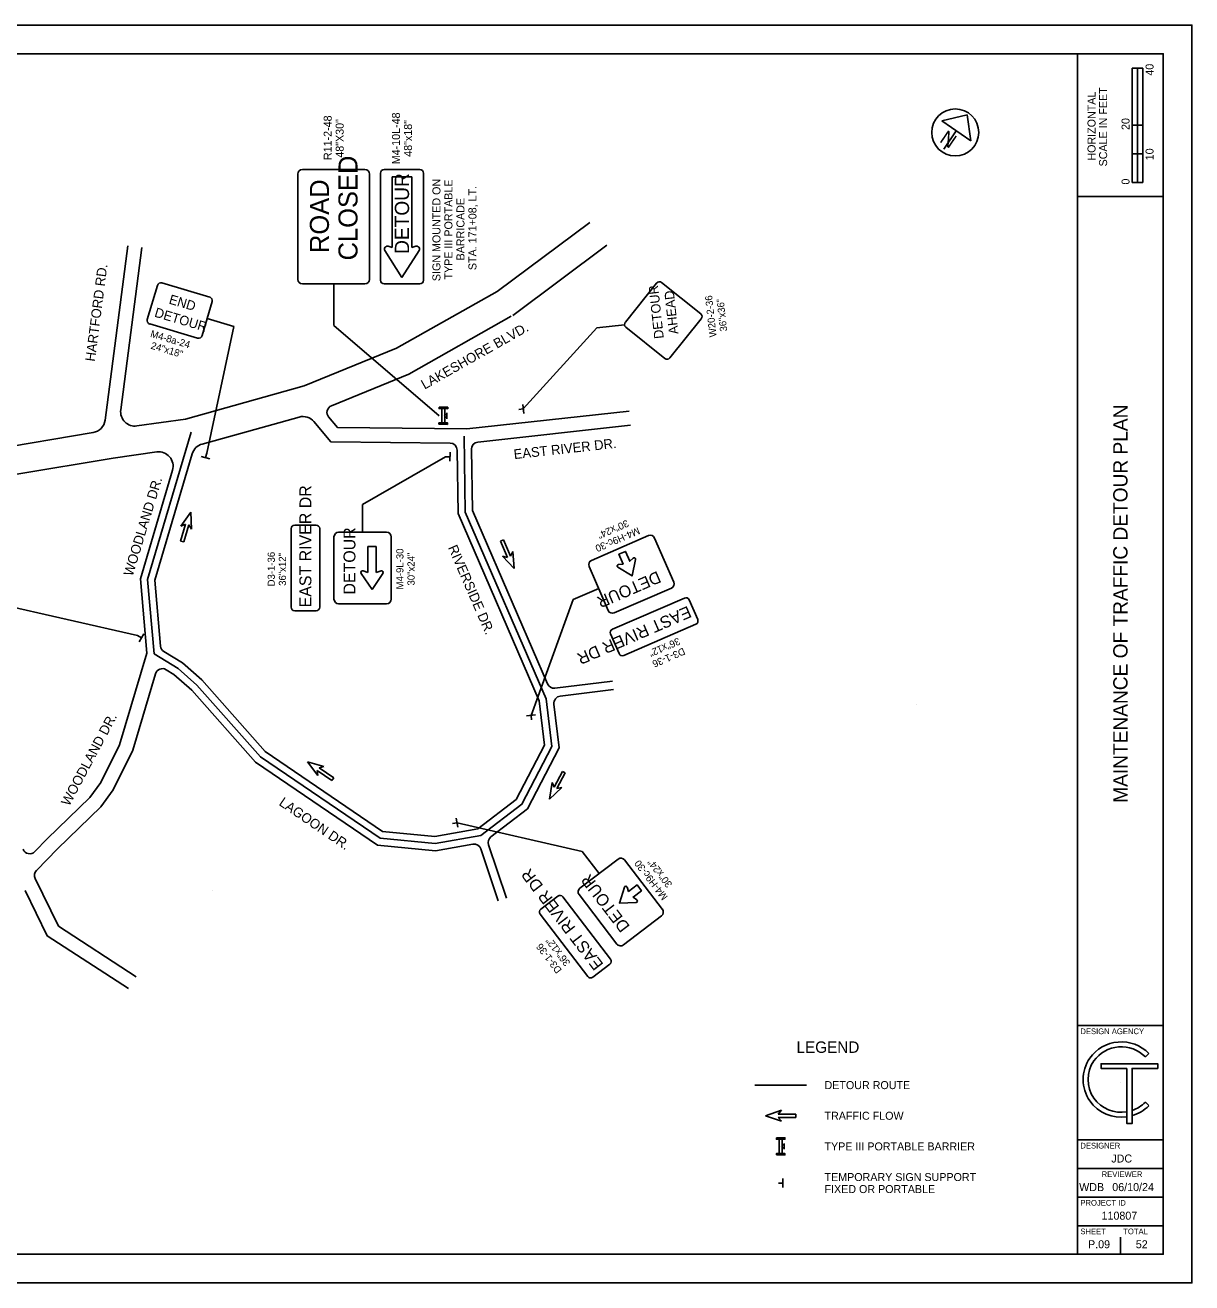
# Model space of a CAD drawing. Extents: x 0 to 680, y 0 to 440.
# Drawn here: x 271.8 to 680, y 0 to 440 of the extents above; entities that cross this region are included whole.
import ezdxf

# ---------------------------------------------------------------- set-up
doc = ezdxf.new("R2010")
doc.units = 0
for name, color, linetype in [('MT_P_Cells', 7, 'Continuous'), ('MT_P_Temp_Road', 7, 'Continuous'), ('PV_X_EOP', 7, 'Continuous'), ('SH_Border', 7, 'Continuous'), ('SH_Cut_Line', 7, 'Continuous'), ('SH_Data', 7, 'Continuous'), ('SH_Masking', 7, 'Continuous'), ('SH_Text', 7, 'Continuous'), ('SN_P_Signs', 7, 'Continuous'), ('SN_P_Text', 7, 'Continuous')]:
    doc.layers.add(name, color=color, linetype=linetype)

msp = doc.modelspace()

# ---------------------------------------------------------------- linework, layer by layer
at = {"layer": 'MT_P_Cells'}
for p, q in [((417.59, 300.84), (417.64, 305.84)), ((418.59, 300.83), (418.64, 305.83)), ((418.62, 303.83), (419.37, 303.82)), ((419.38, 304.32), (419.35, 302.32)), ((446.09, 305.73), (444.5, 305.56)), ((445.91, 307.32), (446.26, 304.14)), ((418.12, 303.34), (418.12, 303.34)), ((418.61, 302.83), (419.36, 302.82)), ((420.46, 290.61), (420.43, 287.41)), ((336.42, 288.24), (333.35, 289.15)), ((334.89, 288.7), (335.34, 290.23)), ((420.45, 289.01), (418.85, 289.02)), ((312.53, 225.63), (311.16, 226.47)), ((313.36, 227), (311.69, 224.27)), ((447.23, 198.34), (450.41, 198.73)), ((448.82, 198.54), (449.01, 196.95)), ((422.94, 160.95), (421.36, 160.67)), ((422.66, 162.52), (423.22, 159.37)), ((535.65, 45.24), (535.65, 50.24)), ((536.65, 45.24), (536.65, 50.24)), ((537.4, 48.74), (537.4, 46.74)), ((536.15, 47.74), (536.15, 47.74)), ((536.65, 48.24), (537.4, 48.24)), ((536.65, 47.24), (537.4, 47.24)), ((536.95, 36.51), (536.95, 33.31)), ((536.95, 34.91), (535.35, 34.91))]:
    msp.add_line(p, q, dxfattribs=at)
for points in [[(416.65, 306.35), (419.65, 306.32), (419.64, 305.82), (416.64, 305.85)], [(416.58, 300.35), (419.58, 300.32), (419.59, 300.82), (416.59, 300.85)], [(534.65, 50.74), (537.65, 50.74), (537.65, 50.24), (534.65, 50.24)], [(534.65, 44.74), (537.65, 44.74), (537.65, 45.24), (534.65, 45.24)]]:
    msp.add_lwpolyline(points, close=True, dxfattribs=at)
at = {"layer": 'MT_P_Temp_Road'}
msp.add_line((545.23, 69.18), (527.06, 69.18), dxfattribs=at)
for points in [[(329.91, 297.58), (314.66, 246.1), (316.9, 220.03)], [(316.9, 220.03), (325.35, 214.87), (331.87, 209.14), (354.12, 184), (396.01, 155.53), (415.23, 153.68), (431.28, 156.5), (445.59, 167.46), (456.13, 187.62), (454.1, 204.3), (425.78, 269.64), (425.4, 296.25)]]:
    msp.add_lwpolyline(points, dxfattribs=at)
at = {"layer": 'PV_X_EOP'}
for p, q in [((469.34, 371), (436.93, 346.85)), ((299.76, 301.75), (307.7, 362.83)), ((305.27, 305.38), (312.66, 362.18)), ((475.31, 362.98), (442.4, 338.46)), ((367.66, 302.88), (333.74, 293.46)), ((483.64, 300), (430.2, 294.13)), ((457.14, 208.06), (477.31, 210.51)), ((459.02, 205.27), (477.68, 207.53)), ((431.28, 151.8), (437.36, 133.65)), ((433.95, 153.27), (440.2, 134.6))]:
    msp.add_line(p, q, dxfattribs=at)
for points in [[(436.93, 346.85), (401.74, 326.97), (369.47, 313.77), (327.91, 302.21), (310.94, 299.79)], [(441.85, 338.15), (406.11, 317.95), (378.95, 306.84)], [(483.1, 304.97), (426.37, 298.74), (381.08, 299.25), (377.99, 302.92)], [(420.5, 293.81), (378.74, 294.27), (372.82, 301.29)], [(295.62, 297.47), (259.75, 291.47), (178.55, 287.16)], [(317.87, 290.68), (302.57, 288.49), (268.91, 282.86)], [(422.97, 291.34), (423.29, 269.1), (451.66, 203.64), (453.55, 188.09), (443.63, 169.11), (430.25, 158.86), (415.14, 156.2), (396.89, 157.96), (355.78, 185.9), (333.64, 210.91), (326.83, 216.89), (320.36, 220.85)], [(427.97, 291.61), (428.27, 270.18), (454.55, 209.55)], [(319.18, 222.77), (317.2, 245.84), (330.29, 290.06)], [(275.2, 150.86), (279.56, 155.36), (294.5, 169.77), (298.31, 175.03), (304.8, 188.23), (314.37, 220.29), (312.13, 246.35), (323.37, 284.31)], [(275.79, 144.3), (283.09, 151.82), (298.29, 166.48), (302.61, 172.45), (309.47, 186.4), (317.44, 213.1)], [(428.47, 153.47), (415.33, 151.16), (395.13, 153.11), (352.45, 182.11), (330.1, 207.36), (323.86, 212.85), (321.14, 214.51)], [(456.84, 202.48), (458.7, 187.15), (447.55, 165.82), (434.8, 156.05)], [(310.65, 107.11), (283.45, 124.83), (275.34, 141.46)], [(307.93, 102.92), (279.57, 121.39), (271.82, 137.28)]]:
    msp.add_lwpolyline(points, dxfattribs=at)
for centre, radius, start, end in [((310.23, 304.74), 5, 172.5857, 278.1351), ((379.9, 304.53), 2.5, 112.2489, 220.1465), ((294.8, 302.4), 5, 279.4984, 352.5857), ((369, 298.07), 5, 40.1465, 105.5343), ((318.57, 285.73), 5, 343.5091, 98.1351), ((335.08, 288.64), 5, 105.5343, 163.5091), ((420.47, 291.31), 2.5, 0.8092, 89.3564), ((430.47, 291.64), 2.5, 96.2649, 180.8092), ((321.67, 222.98), 2.5, 184.9071, 238.5787), ((319.84, 212.38), 2.5, 58.5787, 163.3828), ((456.84, 210.54), 2.5, 203.4328, 276.9327), ((459.32, 202.78), 2.5, 96.9327, 186.9327), ((436.32, 154.06), 2.5, 127.4637, 198.522), ((273.4, 152.6), 2.5, 201.1573, 315.8904), ((428.91, 151.01), 2.5, 18.522, 99.9801), ((277.59, 142.56), 2.5, 135.8904, 206.0049)]:
    msp.add_arc(centre, radius, start, end, dxfattribs=at)
at = {"layer": 'SH_Border'}
for p, q in [((640, 10), (640, 430)), ((640, 380), (670, 380)), ((640, 90), (670, 90)), ((640, 50), (670, 50)), ((640, 40), (670, 40)), ((640, 30), (670, 30)), ((640, 20), (670, 20))]:
    msp.add_line(p, q, dxfattribs=at)
msp.add_lwpolyline([(30, 430), (670, 430), (670, 10), (30, 10)], close=True, dxfattribs=at)
at = {"layer": 'SH_Cut_Line'}
msp.add_lwpolyline([(0, 0), (680, 0), (680, 440), (0, 440)], close=True, dxfattribs=at)
at = {"layer": 'SH_Data'}
for p, q in [((659.13, 385), (659.13, 425)), ((662.88, 425), (659.13, 425)), ((659.13, 405), (659.13, 425)), ((659.13, 425), (661, 425)), ((661, 425), (661.02, 425)), ((661.02, 425), (661.02, 405)), ((662.88, 425), (662.88, 385)), ((661.02, 405), (659.13, 405)), ((662.87, 405), (661, 405)), ((661, 405), (661, 395)), ((662.87, 395), (662.87, 405)), ((661, 395), (659.13, 395)), ((659.13, 395), (659.13, 385)), ((661, 395), (662.87, 395)), ((661, 385), (661, 395)), ((662.88, 385), (659.13, 385)), ((659.13, 385), (661, 385)), ((655, 70), (655, 70)), ((647.5, 13.5), (647.5, 13.5)), ((655, 10), (655, 16))]:
    msp.add_line(p, q, dxfattribs=at)
at = {"layer": 'SH_Masking'}
msp.add_circle((597.22, 402.47), 8.2, dxfattribs=at)
at = {"layer": 'SH_Text'}
for p, q in [((601.44, 408.64), (592.51, 406.48)), ((592.51, 406.48), (602.66, 399.54)), ((602.66, 399.54), (601.44, 408.64)), ((597.59, 403.01), (593.22, 396.62)), ((379.76, 349.48), (379.76, 334.9)), ((335.34, 290.23), (344.81, 334.57)), ((344.81, 334.57), (335.49, 337.33)), ((416.62, 303.35), (379.76, 334.9)), ((481.53, 335.18), (471.87, 334.12)), ((446.09, 305.73), (471.87, 334.12)), ((418.85, 289.02), (389.87, 272.3)), ((329.78, 269.62), (326.31, 264.78)), ((329.78, 269.62), (329.78, 269.62)), ((330.05, 263.67), (329.78, 269.62)), ((389.87, 262.58), (389.87, 272.3)), ((327.96, 265.47), (326.2, 259.53)), ((326.31, 264.78), (327.96, 265.47)), ((327.28, 259.21), (329.04, 265.15)), ((329.04, 265.15), (330.05, 263.67)), ((438.09, 259.47), (439.12, 259.91)), ((438.61, 259.69), (438.61, 259.69)), ((439.12, 259.91), (441.58, 254.24)), ((326.2, 259.53), (327.28, 259.21)), ((326.74, 259.37), (326.74, 259.37)), ((440.55, 253.79), (438.09, 259.47)), ((441.58, 254.24), (442.41, 255.82)), ((442.41, 255.82), (442.86, 249.88)), ((442.86, 249.88), (438.83, 254.27)), ((438.83, 254.27), (440.55, 253.79)), ((442.86, 249.88), (442.86, 249.88)), ((311.16, 226.47), (238, 243.02)), ((472.47, 242.92), (463.55, 239.06)), ((448.82, 198.54), (463.55, 239.06)), ((370.62, 182.24), (370.62, 182.24)), ((370.62, 182.24), (376.37, 180.69)), ((374.17, 177.46), (370.62, 182.24)), ((376.37, 180.69), (374.65, 180.17)), ((379.14, 175.76), (374.02, 179.24)), ((374.02, 179.24), (374.17, 177.46)), ((374.65, 180.17), (379.77, 176.7)), ((379.77, 176.7), (379.14, 175.76)), ((379.45, 176.23), (379.45, 176.23)), ((456.89, 173.44), (459.76, 178.92)), ((460.75, 178.4), (457.89, 172.91)), ((459.76, 178.92), (460.75, 178.4)), ((460.26, 178.66), (460.26, 178.66)), ((455.3, 169.19), (456.18, 175.08)), ((459.64, 173.27), (455.3, 169.19)), ((456.18, 175.08), (456.89, 173.44)), ((457.89, 172.91), (459.64, 173.27)), ((455.3, 169.19), (455.3, 169.19)), ((422.94, 160.95), (466.67, 150.88)), ((472.59, 143.16), (466.67, 150.88)), ((664.98, 80.27), (663.74, 79.05)), ((664.98, 80.27), (663.74, 79.05)), ((668.05, 76.67), (648.27, 76.67)), ((648.27, 76.67), (648.27, 75.02)), ((648.27, 75.02), (657.27, 75.02)), ((657.27, 75.02), (657.27, 55.7)), ((659.11, 55.7), (659.11, 75.02)), ((659.11, 75.02), (668.05, 75.02)), ((668.05, 75.02), (668.05, 76.67)), ((663.74, 63.21), (664.98, 61.99)), ((663.74, 63.21), (664.98, 61.99)), ((530.8, 58.46), (536.43, 60.41)), ((530.8, 58.46), (536.43, 60.41)), ((530.8, 58.46), (530.8, 58.46)), ((536.43, 56.51), (530.8, 58.46)), ((530.8, 58.46), (530.8, 58.46)), ((536.43, 56.51), (530.8, 58.46)), ((536.43, 60.41), (535.3, 59.02)), ((536.43, 60.41), (535.3, 59.02)), ((535.3, 59.02), (541.49, 59.02)), ((535.3, 59.02), (541.49, 59.02)), ((541.49, 57.9), (535.3, 57.9)), ((535.3, 57.9), (536.43, 56.51)), ((541.49, 57.9), (535.3, 57.9)), ((535.3, 57.9), (536.43, 56.51)), ((541.49, 59.02), (541.49, 57.9)), ((541.49, 59.02), (541.49, 57.9)), ((541.49, 58.46), (541.49, 58.46)), ((541.49, 58.46), (541.49, 58.46)), ((657.27, 59.86), (657.27, 58.09)), ((657.27, 59.86), (657.27, 58.09)), ((659.11, 58.5), (659.11, 60.32)), ((659.11, 58.5), (659.11, 60.32)), ((657.27, 55.7), (659.11, 55.7))]:
    msp.add_line(p, q, dxfattribs=at)
msp.add_lwpolyline([(657.27, 75.02), (657.27, 55.7), (659.11, 55.7), (659.11, 75.02), (668.05, 75.02), (668.05, 76.67), (648.27, 76.67), (648.27, 75.02)], close=True, dxfattribs=at)
msp.add_circle((597.22, 402.47), 8.2, dxfattribs=at)
for centre, radius, start, end in [((655.31, 70.7), 13.6, 44.7027, 144.3276), ((655.31, 70.7), 13.6, 44.7027, 144.3276), ((655.31, 70.7), 11.86, 44.7362, 144.1102), ((655.31, 70.7), 11.86, 44.7362, 144.1102), ((655.28, 71.13), 13.33, 145.7329, 214.2671), ((655.28, 71.13), 13.33, 145.7329, 214.2671), ((655.28, 71.13), 11.59, 145.7266, 214.2734), ((655.28, 71.13), 11.59, 145.7266, 214.2734), ((655.31, 71.55), 13.6, 215.6724, 278.2613), ((655.31, 71.55), 13.6, 215.6724, 278.2613), ((655.31, 71.55), 11.86, 215.8898, 279.4882), ((655.31, 71.55), 11.86, 215.8898, 279.4882), ((655.31, 71.55), 11.86, 288.6992, 315.2638), ((655.31, 71.55), 11.86, 288.6992, 315.2638), ((655.31, 71.55), 13.6, 286.2291, 315.2973), ((655.31, 71.55), 13.6, 286.2291, 315.2973)]:
    msp.add_arc(centre, radius, start, end, dxfattribs=at)
at = {"layer": 'SN_P_Signs'}
for p, q in [((400.22, 362.19), (400.22, 386.98)), ((400.22, 386.98), (407.09, 386.98)), ((407.09, 386.98), (407.09, 362.19)), ((403.66, 351.77), (397.68, 361.14)), ((398.83, 362.63), (400.22, 362.19)), ((409.63, 361.14), (403.66, 351.77)), ((407.09, 362.19), (408.48, 362.63)), ((391.74, 248.52), (391.74, 257.58)), ((391.74, 257.58), (394.66, 257.58)), ((394.66, 257.58), (394.66, 248.52)), ((393.2, 242.58), (389.39, 248.2)), ((390.04, 249.06), (391.74, 248.52)), ((397.01, 248.2), (393.2, 242.58)), ((394.66, 248.52), (396.36, 249.06)), ((583.6, 202.3), (583.6, 202.29)), ((337.52, 137.1), (337.52, 137.09))]:
    msp.add_line(p, q, dxfattribs=at)
for points in [[(367.26, 351.04), (367.26, 387.91)], [(368.82, 389.48), (390.69, 389.48)], [(392.26, 387.91), (392.26, 351.04)], [(396.16, 388.23), (396.16, 350.73)], [(409.91, 389.48), (397.41, 389.48)], [(411.16, 350.73), (411.16, 388.23)], [(318.08, 348.95), (314.56, 337.06)], [(336.38, 344.89), (319.69, 349.83)], [(390.69, 349.48), (368.82, 349.48)], [(397.41, 349.48), (409.91, 349.48)], [(481.8, 336.1), (492.75, 349.75)], [(494.51, 349.95), (508.16, 339)], [(333.73, 331.39), (337.25, 343.28)], [(315.43, 335.45), (332.12, 330.51)], [(508.35, 337.24), (497.4, 323.59)], [(495.64, 323.4), (481.99, 334.35)], [(379.87, 239.18), (379.87, 260.98)], [(381.47, 262.58), (398.27, 262.58)], [(399.87, 260.98), (399.87, 239.18)], [(398.27, 237.58), (381.47, 237.58)]]:
    msp.add_lwpolyline(points, dxfattribs=at)
for centre, radius, start, end in [((368.82, 387.91), 1.57, 90, 180), ((390.69, 387.91), 1.57, 0, 90), ((397.41, 388.23), 1.25, 90, 180), ((409.91, 388.23), 1.25, 0, 90), ((398.52, 361.68), 1, 72.1811, 212.5109), ((408.79, 361.68), 1, 327.4891, 107.8189), ((319.32, 348.58), 1.3, 73.5091, 163.5091), ((368.82, 351.04), 1.57, 180, 270), ((390.69, 351.04), 1.57, 270, 0), ((397.41, 350.73), 1.25, 180, 270), ((409.91, 350.73), 1.25, 270, 0), ((493.72, 348.97), 1.25, 51.2649, 141.2649), ((336.01, 343.65), 1.3, 343.5091, 73.5091), ((507.38, 338.02), 1.25, 321.2649, 51.2649), ((315.8, 336.69), 1.3, 163.5091, 253.5091), ((482.77, 335.32), 1.25, 141.2649, 231.2649), ((332.49, 331.76), 1.3, 253.5091, 343.5091), ((496.43, 324.37), 1.25, 231.2649, 321.2649), ((381.47, 260.98), 1.6, 90, 180), ((398.27, 260.98), 1.6, 360, 90), ((389.87, 248.52), 0.572, 72.1992, 214.1969), ((396.53, 248.52), 0.572, 325.8031, 107.8008), ((381.47, 239.18), 1.6, 180, 270), ((398.27, 239.18), 1.6, 270, 360)]:
    msp.add_arc(centre, radius, start, end, dxfattribs=at)
at = {"layer": 'SN_P_Text'}
for p, q in [((481.85, 255.87), (479.53, 254.87)), ((483.32, 252.49), (481.85, 255.87)), ((481.01, 251.47), (479.4, 251.3)), ((483.33, 252.47), (483.32, 252.49)), ((484.55, 253.53), (483.33, 252.47)), ((484.17, 247.34), (485.35, 253.06)), ((479.19, 250.39), (484.17, 247.34)), ((481.46, 138.45), (479.71, 132.88)), ((482.95, 136.95), (482.4, 138.47)), ((484.5, 134.95), (487.43, 137.19)), ((487.43, 137.19), (485.89, 139.2)), ((479.71, 132.88), (485.55, 133.12)), ((484.49, 134.94), (484.5, 134.95)), ((485.81, 134.02), (484.49, 134.94))]:
    msp.add_line(p, q, dxfattribs=at)
for points in [[(366.12, 265.11), (373.62, 265.11)], [(364.87, 263.86), (364.87, 236.36)], [(374.87, 236.36), (374.87, 263.86)], [(489.96, 261.4), (469.96, 252.73)], [(498.74, 245.16), (492.06, 260.57)], [(479.4, 251.3), (481.01, 251.47), (479.53, 254.87), (481.85, 255.87), (483.33, 252.47), (484.55, 253.53)], [(485.35, 253.06), (484.17, 247.34), (479.19, 250.39)], [(479.53, 254.87), (481, 251.48)], [(469.12, 250.63), (475.81, 235.22)], [(477.91, 234.38), (497.91, 243.05)], [(502.49, 239.59), (477.26, 228.65)], [(507.11, 232.06), (504.13, 238.94)], [(366.12, 235.11), (373.62, 235.11)], [(481.23, 219.48), (506.46, 230.41)], [(479.59, 220.13), (476.61, 227.01)], [(479.25, 148.27), (465.92, 138.05)], [(494.76, 130.67), (481.5, 147.98)], [(485.55, 133.12), (479.71, 132.88), (481.46, 138.45)], [(482.4, 138.47), (482.95, 136.95), (485.89, 139.2), (487.43, 137.19), (484.49, 134.94), (485.81, 134.02)], [(485.89, 139.2), (482.96, 136.96)], [(452.2, 130.73), (458.15, 135.29)], [(476.63, 113.23), (459.9, 135.06)], [(465.62, 135.81), (478.88, 118.51)], [(451.96, 128.97), (468.69, 107.15)], [(481.13, 118.21), (494.46, 128.43)], [(470.44, 106.91), (476.4, 111.48)]]:
    msp.add_lwpolyline(points, dxfattribs=at)
for centre, radius, start, end in [((366.12, 263.86), 1.25, 90, 180), ((373.62, 263.86), 1.25, 0, 90), ((490.59, 259.94), 1.6, 23.4328, 113.4328), ((470.59, 251.27), 1.6, 113.4328, 203.4328), ((479.45, 250.81), 0.493, 95.795, 238.5121), ((479.45, 250.81), 0.493, 95.795, 238.5121), ((484.87, 253.16), 0.493, 348.3536, 131.0707), ((484.87, 253.16), 0.493, 348.3536, 131.0707), ((497.28, 244.52), 1.6, 293.4328, 23.4328), ((502.99, 238.44), 1.25, 23.4328, 113.4328), ((366.12, 236.36), 1.25, 180, 270), ((373.62, 236.36), 1.25, 270, 0), ((477.27, 235.85), 1.6, 203.4328, 293.4328), ((505.97, 231.56), 1.25, 293.4328, 23.4328), ((477.75, 227.5), 1.25, 113.4328, 203.4328), ((480.74, 220.62), 1.25, 203.4328, 293.4328), ((480.23, 147), 1.6, 37.4637, 127.4637), ((466.89, 136.78), 1.6, 127.4637, 217.4637), ((481.93, 138.3), 0.493, 19.8259, 162.5429), ((481.93, 138.3), 0.493, 19.8259, 162.5429), ((458.91, 134.3), 1.25, 37.4637, 127.4637), ((485.53, 133.61), 0.493, 272.3844, 55.1015), ((485.53, 133.61), 0.493, 272.3844, 55.1015), ((452.96, 129.73), 1.25, 127.4637, 217.4637), ((493.49, 129.7), 1.6, 307.4637, 37.4637), ((480.15, 119.48), 1.6, 217.4637, 307.4637), ((475.64, 112.47), 1.25, 307.4637, 37.4637), ((469.68, 107.91), 1.25, 217.4637, 307.4637)]:
    msp.add_arc(centre, radius, start, end, dxfattribs=at)

# ---------------------------------------------------------------- texts
at = {"layer": 'SH_Data'}
for s, height, p in [('40', 2.8, (666.61, 422.33)), ('SCALE IN FEET', 2.8, (650.35, 390.58)), ('HORIZONTAL', 2.8, (646.3, 392.61)), ('20', 2.8, (658.21, 403.33)), ('10', 2.8, (666.61, 392.73)), ('0', 2.8, (658.21, 384.23)), ('MAINTENANCE OF TRAFFIC DETOUR PLAN', 5, (657.5, 167.95))]:
    msp.add_text(s, height=height, rotation=90, dxfattribs=at).set_placement(p)
for s, height, p in [('DESIGN AGENCY', 2, (641, 87)), ('DESIGNER', 2, (641, 47)), ('JDC', 2.8, (651.82, 42.1)), ('REVIEWER', 2, (648.44, 37)), ('WDB', 2.8, (640.58, 32.1)), ('06/10/24', 2.8, (652.16, 32.1)), ('PROJECT ID', 2, (641, 27)), ('110807', 2.8, (648.4, 22.1)), ('SHEET', 2, (641, 17)), ('TOTAL', 2, (656, 17)), ('P.09', 2.8, (643.68, 12.1)), ('52', 2.8, (660.39, 12.1))]:
    msp.add_text(s, height=height, dxfattribs=at).set_placement(p)
at = {"layer": 'SH_Text'}
for s, height, rotation, p in [('N', 5, 325.6351, (591.43, 399.37)), ('HARTFORD RD.', 3.4, 82.5857, (296.21, 322.18)), ('LAKESHORE BLVD.', 3.4, 29.4699, (411.57, 312.47)), ('EAST RIVER DR.', 3.4, 6.2649, (442.94, 288.17)), ('WOODLAND DR.', 3.4, 73.1504, (309.42, 247)), ('RIVERSIDE DR.', 3.4, 293.4328, (419.69, 257.25)), ('WOODLAND DR.', 3.4, 61.9386, (287.22, 166.55)), ('LAGOON DR.', 3.4, 325.7985, (360.35, 167.31)), ('LEGEND', 4, 360, (541.68, 80.46))]:
    msp.add_text(s, height=height, rotation=rotation, dxfattribs=at).set_placement(p)
for s, p in [('DETOUR ROUTE', (551.49, 67.78)), ('TRAFFIC FLOW', (551.49, 57.06)), ('TYPE III PORTABLE BARRIER', (551.49, 46.34)), ('TEMPORARY SIGN SUPPORT', (551.49, 35.61)), ('FIXED OR PORTABLE', (551.49, 31.41))]:
    msp.add_text(s, height=2.8, dxfattribs=at).set_placement(p)
at = {"layer": 'SN_P_Signs'}
for s, height, rotation, p in [('CLOSED', 6.667, 90, (388.1, 357.69)), ('DETOUR', 5, 90, (406.14, 359.98)), ('ROAD', 6.667, 90, (378.1, 360.28)), ('DETOUR', 3.333, 96.2649, (495.27, 330.46)), ('END', 3.333, 343.5091, (321.88, 342.64)), ('AHEAD', 3.333, 96.2649, (500.4, 332.03)), ('DETOUR', 3.333, 343.5091, (316.83, 338.07)), ('DETOUR', 4.167, 90, (387.37, 240.79))]:
    msp.add_text(s, height=height, rotation=rotation, dxfattribs=at).set_placement(p)
at = {"layer": 'SN_P_Text'}
for s, height, rotation, p in [('M4-10L-48', 2.8, 90, (402.96, 391.34)), ('R11-2-48', 2.8, 90, (379.06, 392.8)), ('48"X30"', 2.8, 90, (383.26, 393.64)), ('48"x18"', 2.8, 90, (407.16, 393.95)), ('SIGN MOUNTED ON', 2.8, 90, (417.11, 350.45)), ('TYPE III PORTABLE', 2.8, 90, (421.31, 351.03)), ('STA. 171+08, LT.', 2.8, 90, (429.71, 354.3)), ('BARRICADE', 2.8, 90, (425.51, 357.7)), ('W20-2-36', 2.5, 96.2649, (513.73, 330.99)), ('36"x36"', 2.5, 96.2649, (517.44, 332.96)), ('M4-8a-24', 2.5, 343.5091, (315.41, 330.97)), ('24"x18"', 2.5, 343.5091, (315.57, 326.85)), ('EAST RIVER DR', 4.1667, 90, (371.95, 236.31)), ('M4-H9c-30', 2.5, 203.4328, (486.19, 264.45)), ('30"x24"', 2.5, 203.4328, (482.32, 267.03)), ('D3-1-36', 2.5, 90, (359.17, 243.65)), ('M4-9L-30', 2.5, 90, (404.17, 242.59)), ('30"x24"', 2.5, 90, (408.07, 243.96)), ('36"x12"', 2.5, 90, (363.07, 243.85)), ('DETOUR', 4.167, 203.4328, (493.05, 249.12)), ('EAST RIVER DR', 4.1667, 203.4328, (503.69, 236.93)), ('36"x12"', 2.5, 203.4328, (500.31, 225.78)), ('D3-1-36', 2.5, 203.4328, (502.04, 222.28)), ('M4-H9c-30', 2.5, 127.4637, (496.8, 135.07)), ('30"x24"', 2.5, 127.4637, (498.36, 139.45)), ('EAST RIVER DR', 4.1667, 127.4637, (474.34, 111.41)), ('DETOUR', 4.167, 127.4637, (483.59, 124.7)), ('36"x12"', 2.5, 127.4637, (462.71, 112)), ('D3-1-36', 2.5, 127.4637, (459.73, 109.46))]:
    msp.add_text(s, height=height, rotation=rotation, dxfattribs=at).set_placement(p)

doc.saveas('drawing.dxf')
